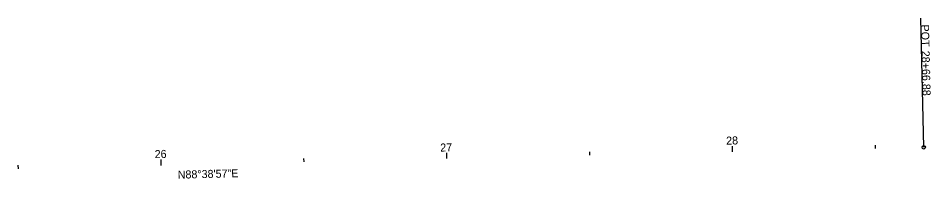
# Model space of a CAD drawing. Extents: x 2273904 to 2275374, y 654586 to 654897.
# Drawn here: x 2275055.2 to 2275374.4, y 654698.3 to 654754.2 of the extents above; entities that cross this region are included whole.
import ezdxf

# ---------------------------------------------------------------- set-up
doc = ezdxf.new("R2010")
doc.units = 0
for name, color, linetype in [('DR_P_Ditch', 7, 'Continuous'), ('DR_P_Erosion_Control', 7, 'Continuous'), ('GK_Drainage_Nodes', 7, 'Continuous'), ('SC_Scratch1', 7, 'Continuous'), ('SC_Scratch10', 7, 'Continuous')]:
    doc.layers.add(name, color=color, linetype=linetype)

msp = doc.modelspace()

# ---------------------------------------------------------------- linework, layer by layer
at = {"layer": 'DR_P_Ditch'}
for p, q in [((2275371.97, 654709.22), (2275370.91, 654754.21)), ((2275305.11, 654707.65), (2275305.08, 654708.85)), ((2275105.17, 654702.93), (2275105.14, 654704.13)), ((2275205.14, 654705.29), (2275205.11, 654706.49))]:
    msp.add_line(p, q, dxfattribs=at)
msp.add_circle((2275371.97, 654709.22), 0.6, dxfattribs=at)
at = {"layer": 'DR_P_Erosion_Control'}
for p, q in [((2275371.97, 654709.22), (2275370.91, 654754.21)), ((2275255.12, 654706.47), (2275255.1, 654707.67)), ((2275305.11, 654707.65), (2275305.06, 654709.65)), ((2275355.1, 654708.82), (2275355.07, 654710.02)), ((2275105.17, 654702.93), (2275105.12, 654704.93)), ((2275155.15, 654704.11), (2275155.12, 654705.31)), ((2275205.14, 654705.29), (2275205.09, 654707.29)), ((2275055.18, 654701.75), (2275055.15, 654702.95))]:
    msp.add_line(p, q, dxfattribs=at)
msp.add_circle((2275371.97, 654709.22), 0.6, dxfattribs=at)
at = {"layer": 'SC_Scratch1'}
msp.add_line((2275371.97, 654709.22), (2275370.91, 654754.21), dxfattribs=at)
msp.add_circle((2275371.97, 654709.22), 0.6, dxfattribs=at)

# ---------------------------------------------------------------- texts
at = {"layer": 'DR_P_Ditch'}
for s, p in [('POT', (2275371.01, 654752)), ('28+66.88', (2275371.22, 654742.87))]:
    msp.add_text(s, height=2.8, rotation=271.351, dxfattribs=at).set_placement(p)
at = {"layer": 'DR_P_Erosion_Control'}
for s, rotation, p in [('POT', 271.351, (2275371.01, 654752)), ('28+66.88', 271.351, (2275371.22, 654742.87)), ('27', 1.351, (2275202.83, 654707.73)), ('28', 1.351, (2275302.86, 654710.14)), ('26', 1.351, (2275102.91, 654705.43))]:
    msp.add_text(s, height=2.8, rotation=rotation, dxfattribs=at).set_placement(p)
at = {"layer": 'GK_Drainage_Nodes'}
msp.add_text('N88°38\'57"E', height=2.8, rotation=1.351, dxfattribs=at).set_placement((2275110.98, 654698.27))
msp.add_text('N88°38\'57"E', height=2.8, rotation=1.351, dxfattribs=at).set_placement((2275110.98, 654698.27))
at = {"layer": 'SC_Scratch1'}
for s, p in [('POT', (2275371.01, 654752)), ('28+66.88', (2275371.22, 654742.87))]:
    msp.add_text(s, height=2.8, rotation=271.351, dxfattribs=at).set_placement(p)
at = {"layer": 'SC_Scratch10'}
msp.add_text('N88°38\'57"E', height=2.8, rotation=1.351, dxfattribs=at).set_placement((2275110.98, 654698.27))

doc.saveas('drawing.dxf')
